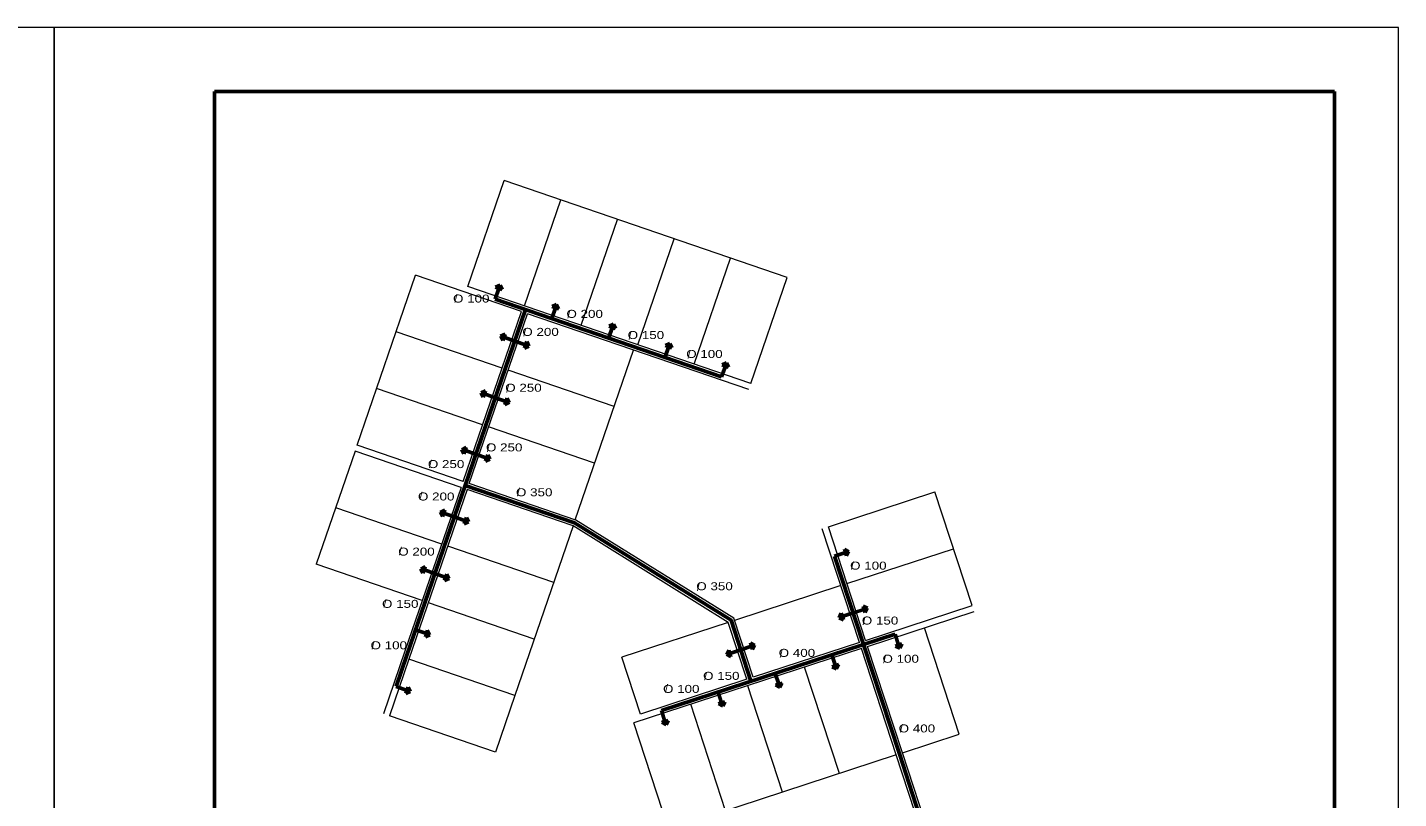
# Model space of a CAD drawing. Extents: x 312964 to 351929, y 9004151 to 9034973.
# Drawn here: x 329279 to 333563, y 9007681 to 9010091 of the extents above; entities that cross this region are included whole.
import ezdxf
from ezdxf.enums import TextEntityAlignment as Align

# ---------------------------------------------------------------- set-up
doc = ezdxf.new("R2010")
doc.units = 0
doc.header["$LTSCALE"] = 10
doc.layers.add('1', color=7, linetype='Continuous', lineweight=13)
doc.layers.add('2', color=7, linetype='Continuous', lineweight=53)

msp = doc.modelspace()

# ---------------------------------------------------------------- linework, layer by layer
at = {"layer": '1', "lineweight": 53}
for p, q in [((329862.66, 9009891.43), (329862.66, 9004351.43)), ((333362.66, 9009891.43), (329862.66, 9009891.43)), ((333362.66, 9004351.43), (333362.66, 9009891.43))]:
    msp.add_line(p, q, dxfattribs=at)
at = {"layer": '1'}
for p, q in [((330654.76, 9009281.53), (330768.3, 9009612.61)), ((331652.74, 9009309.31), (330768.3, 9009612.61)), ((330831.65, 9009220.87), (330945.19, 9009551.95)), ((331008.54, 9009160.21), (331122.07, 9009491.29)), ((331185.43, 9009099.56), (331298.96, 9009430.63)), ((331362.32, 9009038.9), (331475.85, 9009369.97)), ((330309.09, 9008785.86), (330491.07, 9009316.52)), ((330822.14, 9009202.99), (330491.07, 9009316.52)), ((331539.21, 9008978.24), (331652.74, 9009309.31)), ((331539.21, 9008978.24), (330654.76, 9009281.53)), ((330640.17, 9008672.33), (330822.14, 9009202.99)), ((330659.08, 9008665.84), (330841.06, 9009196.5)), ((331532.72, 9008959.32), (330841.06, 9009196.5)), ((330761.48, 9009026.1), (330430.41, 9009139.63)), ((330990.16, 9008552.31), (331172.13, 9009082.97)), ((331111.48, 9008906.08), (330780.4, 9009019.62)), ((330700.82, 9008849.21), (330369.75, 9008962.75)), ((331050.82, 9008729.19), (330719.74, 9008842.73)), ((330640.17, 9008672.33), (330309.09, 9008785.86)), ((330302.6, 9008766.94), (330181.29, 9008413.16)), ((330633.68, 9008653.41), (330302.6, 9008766.94)), ((330633.68, 9008653.41), (330458.19, 9008141.66)), ((330992.31, 9008551.57), (330659.08, 9008665.84)), ((330652.6, 9008646.92), (330470.62, 9008116.25)), ((330983.67, 9008533.39), (330652.6, 9008646.92)), ((331781.04, 9008530.72), (332113.69, 9008639.56)), ((332229.99, 9008284.1), (332113.69, 9008639.56)), ((330573.02, 9008476.52), (330241.94, 9008590.05)), ((330983.67, 9008533.39), (330801.69, 9008002.72)), ((331468.53, 9008231.72), (330983.67, 9008533.39)), ((331485.27, 9008244.85), (330992.31, 9008551.57)), ((331878.34, 9008169.04), (331762.04, 9008524.5)), ((331897.34, 9008175.26), (331781.04, 9008530.72)), ((330923.01, 9008356.5), (330591.94, 9008470.03)), ((331839.19, 9008352.99), (332171.84, 9008461.83)), ((330512.36, 9008299.63), (330181.29, 9008413.16)), ((331820.19, 9008346.77), (331487.54, 9008237.93)), ((330862.35, 9008179.61), (330531.28, 9008293.14)), ((331897.34, 9008175.26), (332229.99, 9008284.1)), ((331468.53, 9008231.72), (331135.88, 9008122.88)), ((331526.68, 9008053.99), (331468.53, 9008231.72)), ((331545.69, 9008060.21), (331485.27, 9008244.85)), ((331903.56, 9008156.25), (332236.21, 9008265.09)), ((332190.13, 9007881.76), (332081.29, 9008214.4)), ((330458.19, 9008141.66), (330391.04, 9007945.85)), ((331884.55, 9008150.03), (331173.64, 9007917.43)), ((331878.34, 9008169.04), (331545.69, 9008060.21)), ((331993.39, 9007817.39), (331884.55, 9008150.03)), ((332012.4, 9007823.61), (331903.56, 9008156.25)), ((330470.62, 9008116.25), (330409.96, 9007939.37)), ((330801.69, 9008002.72), (330470.62, 9008116.25)), ((331194.03, 9007945.15), (331135.88, 9008122.88)), ((331526.68, 9008053.99), (331194.03, 9007945.15)), ((331815.66, 9007759.24), (331706.83, 9008091.88)), ((331637.93, 9007701.09), (331529.1, 9008033.73)), ((330801.69, 9008002.72), (330741.04, 9007825.83)), ((331460.2, 9007642.94), (331351.37, 9007975.58)), ((330741.04, 9007825.83), (330409.96, 9007939.37)), ((331282.48, 9007584.79), (331173.64, 9007917.43)), ((332012.4, 9007823.61), (332190.13, 9007881.76)), ((331993.39, 9007817.39), (331282.48, 9007584.79)), ((332051.54, 9007639.66), (331993.39, 9007817.39))]:
    msp.add_line(p, q, dxfattribs=at)
for points in [[(325162.66, 9010091.43), (325162.66, 9004151.43), (329362.66, 9004151.43), (329362.66, 9010091.43)], [(329362.66, 9010091.43), (329362.66, 9004151.43), (333562.66, 9004151.43), (333562.66, 9010091.43)]]:
    msp.add_lwpolyline(points, close=True, dxfattribs=at)
msp.add_lwpolyline([(332294.44, 9006961.57), (332185.61, 9007294.22), (332012.4, 9007823.61)], dxfattribs=at)
at = {"layer": '2'}
for p, q in [((330751.91, 9009275.54), (330739.97, 9009241.74)), ((330755.26, 9009285.79), (330741.5, 9009279.22)), ((330761.83, 9009272.04), (330741.5, 9009279.22)), ((330755.26, 9009285.79), (330761.83, 9009272.04)), ((330646.38, 9008659.62), (330834.84, 9009209.21)), ((331447.52, 9008999.11), (330739.97, 9009241.74)), ((330928.74, 9009214.9), (330916.8, 9009181.1)), ((330932.09, 9009225.15), (330918.33, 9009218.58)), ((330938.66, 9009211.4), (330918.33, 9009218.58)), ((330932.09, 9009225.15), (330938.66, 9009211.4)), ((330757.04, 9009126.06), (330770.79, 9009132.63)), ((330757.04, 9009126.06), (330763.61, 9009112.31)), ((330770.79, 9009132.63), (330763.61, 9009112.31)), ((331106.52, 9009153.94), (331094.58, 9009120.14)), ((331109.87, 9009164.19), (331096.12, 9009157.62)), ((331116.44, 9009150.43), (331096.12, 9009157.62)), ((331109.87, 9009164.19), (331116.44, 9009150.43)), ((330767.29, 9009122.71), (330801.09, 9009110.77)), ((330834.89, 9009098.83), (330801.09, 9009110.77)), ((330831.38, 9009088.91), (330838.57, 9009109.23)), ((330845.14, 9009095.48), (330831.38, 9009088.91)), ((330845.14, 9009095.48), (330838.57, 9009109.23)), ((331282.45, 9009093.61), (331270.5, 9009059.81)), ((331285.8, 9009103.86), (331272.04, 9009097.29)), ((331292.37, 9009090.1), (331272.04, 9009097.29)), ((331285.8, 9009103.86), (331292.37, 9009090.1)), ((331462.81, 9009043.16), (331449.06, 9009036.59)), ((331462.81, 9009043.16), (331469.38, 9009029.4)), ((331459.46, 9009032.91), (331447.52, 9008999.11)), ((331469.38, 9009029.4), (331449.06, 9009036.59)), ((330696.38, 9008949.18), (330710.14, 9008955.75)), ((330710.14, 9008955.75), (330702.95, 9008935.42)), ((330696.38, 9008949.18), (330702.95, 9008935.42)), ((330706.63, 9008945.83), (330740.43, 9008933.89)), ((330774.23, 9008921.94), (330740.43, 9008933.89)), ((330770.73, 9008912.02), (330777.91, 9008932.35)), ((330784.48, 9008918.6), (330770.73, 9008912.02)), ((330784.48, 9008918.6), (330777.91, 9008932.35)), ((330635.74, 9008772.35), (330649.5, 9008778.92)), ((330635.74, 9008772.35), (330642.31, 9008758.59)), ((330649.5, 9008778.92), (330642.31, 9008758.59)), ((330645.99, 9008769), (330679.79, 9008757.06)), ((330713.59, 9008745.11), (330679.79, 9008757.06)), ((330710.09, 9008735.19), (330717.27, 9008755.52)), ((330723.84, 9008741.76), (330710.09, 9008735.19)), ((330723.84, 9008741.76), (330717.27, 9008755.52)), ((330568.59, 9008576.53), (330582.35, 9008583.1)), ((330568.59, 9008576.53), (330575.16, 9008562.77)), ((330582.35, 9008583.1), (330575.16, 9008562.77)), ((330578.84, 9008573.18), (330612.64, 9008561.24)), ((330646.44, 9008549.29), (330612.64, 9008561.24)), ((330642.94, 9008539.37), (330650.12, 9008559.7)), ((330656.69, 9008545.95), (330642.94, 9008539.37)), ((330656.69, 9008545.95), (330650.12, 9008559.7)), ((331834.69, 9008449.88), (331800.61, 9008438.75)), ((331837.96, 9008439.88), (331831.26, 9008460.37)), ((331844.85, 9008453.48), (331831.26, 9008460.37)), ((331844.85, 9008453.48), (331837.96, 9008439.88)), ((330507.86, 9008399.42), (330521.61, 9008405.99)), ((330507.86, 9008399.42), (330514.43, 9008385.67)), ((330521.61, 9008405.99), (330514.43, 9008385.67)), ((330518.11, 9008396.07), (330551.91, 9008384.13)), ((330585.71, 9008372.19), (330551.91, 9008384.13)), ((330582.2, 9008362.27), (330589.39, 9008382.59)), ((330595.96, 9008368.84), (330582.2, 9008362.27)), ((330595.96, 9008368.84), (330589.39, 9008382.59)), ((331892.84, 9008272.15), (331858.76, 9008261.02)), ((331896.11, 9008262.15), (331889.41, 9008282.65)), ((331903, 9008275.75), (331889.41, 9008282.65)), ((331903, 9008275.75), (331896.11, 9008262.15)), ((331814.52, 9008246.29), (331821.42, 9008259.88)), ((331814.52, 9008246.29), (331828.12, 9008239.39)), ((331821.42, 9008259.88), (331828.12, 9008239.39)), ((331824.69, 9008249.88), (331858.76, 9008261.02)), ((330525.43, 9008196.42), (330491.63, 9008208.36)), ((330521.93, 9008186.5), (330529.11, 9008206.82)), ((330535.68, 9008193.07), (330521.93, 9008186.5)), ((330535.68, 9008193.07), (330529.11, 9008206.82)), ((331890.95, 9008162.65), (331989.32, 9008194.83)), ((332000.45, 9008160.76), (331989.32, 9008194.83)), ((331890.95, 9008162.65), (331259.39, 9007956.01)), ((331462.87, 9008131.23), (331469.77, 9008144.82)), ((331469.77, 9008144.82), (331476.46, 9008124.33)), ((331473.03, 9008134.82), (331507.11, 9008145.96)), ((331541.18, 9008157.1), (331507.11, 9008145.96)), ((331544.45, 9008147.1), (331537.75, 9008167.59)), ((331551.35, 9008160.69), (331537.75, 9008167.59)), ((331551.35, 9008160.69), (331544.45, 9008147.1)), ((331990.45, 9008157.49), (332010.95, 9008164.19)), ((332004.05, 9008150.59), (331990.45, 9008157.49)), ((332004.05, 9008150.59), (332010.95, 9008164.19)), ((331462.87, 9008131.23), (331476.46, 9008124.33)), ((331803.07, 9008096.18), (331791.94, 9008130.25)), ((331793.07, 9008092.91), (331813.56, 9008099.61)), ((331806.67, 9008086.01), (331813.56, 9008099.61)), ((331625.96, 9008038.23), (331614.82, 9008072.3)), ((331806.67, 9008086.01), (331793.07, 9008092.91)), ((330464.63, 9008019.11), (330430.83, 9008031.05)), ((330461.13, 9008009.19), (330468.31, 9008029.52)), ((330474.88, 9008015.76), (330461.13, 9008009.19)), ((330474.88, 9008015.76), (330468.31, 9008029.52)), ((331447.58, 9007979.87), (331436.45, 9008013.94)), ((331615.96, 9008034.96), (331636.45, 9008041.66)), ((331629.56, 9008028.06), (331615.96, 9008034.96)), ((331629.56, 9008028.06), (331636.45, 9008041.66)), ((331437.58, 9007976.6), (331458.08, 9007983.3)), ((331451.18, 9007969.7), (331437.58, 9007976.6)), ((331451.18, 9007969.7), (331458.08, 9007983.3)), ((331270.53, 9007921.94), (331259.39, 9007956.01)), ((331260.53, 9007918.67), (331281.02, 9007925.37)), ((331274.12, 9007911.77), (331281.02, 9007925.37)), ((331274.12, 9007911.77), (331260.53, 9007918.67))]:
    msp.add_line(p, q, dxfattribs=at)
for points in [[(331539.29, 9008047.59), (331476.9, 9008238.28), (330987.99, 9008542.48), (330646.38, 9008659.62), (330464.4, 9008128.96), (330430.83, 9008031.05)], [(332064.16, 9007633.26), (332002.9, 9007820.5), (331890.95, 9008162.65), (331800.61, 9008438.75)]]:
    msp.add_lwpolyline(points, dxfattribs=at)

# ---------------------------------------------------------------- texts
at = {"layer": '2', "width": 1.25}
for s, p in [('O 100', (330665.37, 9009231.27)), ('O 200', (331019.78, 9009183.41)), ('O 200', (330881.95, 9009127.11)), ('O 150', (331211.06, 9009117.25)), ('O 100', (331393.89, 9009058.14)), ('O 250', (330828.51, 9008952.57)), ('O 250', (330768.21, 9008766.02)), ('O 250', (330586.78, 9008713.94)), ('O 200', (330555.84, 9008612.59)), ('O 350', (330862.05, 9008625.73)), ('O 200', (330494.14, 9008440.32)), ('O 100', (331906.03, 9008396.5)), ('O 350', (331425.54, 9008332.02)), ('O 150', (330443.51, 9008277.04)), ('O 150', (331942.6, 9008224.78)), ('O 100', (330407.7, 9008147.45)), ('O 400', (331682.91, 9008123.7)), ('O 100', (332007.13, 9008105.43)), ('O 150', (331446.63, 9008051.91)), ('O 100', (331321.46, 9008011.09)), ('O 400', (332057.74, 9007887.61))]:
    msp.add_text(s, height=25, dxfattribs=at).set_placement(p, align=Align.CENTER)
at = {"layer": '2'}
for p in [(330617.4, 9009231.25), (330970.41, 9009181.99), (330832.58, 9009125.68), (331161.68, 9009115.83), (331345.93, 9009056.71), (330779.14, 9008949.74), (330719.06, 9008764.7), (330537.63, 9008714.03), (330812.54, 9008625.96), (330508.1, 9008614.09), (330443.6, 9008441.48), (331856.11, 9008396.53), (331375.11, 9008330.37), (330395.78, 9008278.2), (331892.67, 9008223.4), (330358.57, 9008147.2), (331633.89, 9008122.05), (331956.97, 9008104.23), (331397.61, 9008050.27), (331275.26, 9008012.26), (332009.01, 9007887.47)]:
    msp.add_text('/', height=25, dxfattribs=at).set_placement(p, align=Align.CENTER)

doc.saveas('drawing.dxf')
